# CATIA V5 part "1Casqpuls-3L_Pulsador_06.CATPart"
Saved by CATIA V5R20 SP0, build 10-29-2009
Part number: 1Casqpuls-3L_Pulsador_06
Revision: ANY
Definition: UNKNOWN
Nomenclature: 1Casqpuls-3L_Pulsador_06
Source: Unknown
Bounding box of the stored display mesh (mm): x -5.3 to 5.3, y 0 to 15.3, z -5.3 to 5.3
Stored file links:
  C:\Users\Utente\Desktop\IO LAVORO\3D X SITO CF\CUMSA\3D files AE\AE 031620\1Casqpuls-3L_Pulsador_06.CATPart
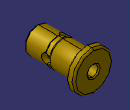
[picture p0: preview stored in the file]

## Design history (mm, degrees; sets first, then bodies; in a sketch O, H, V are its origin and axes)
Body1 "MatrizC1" (main body)
  Solid1: solid without history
